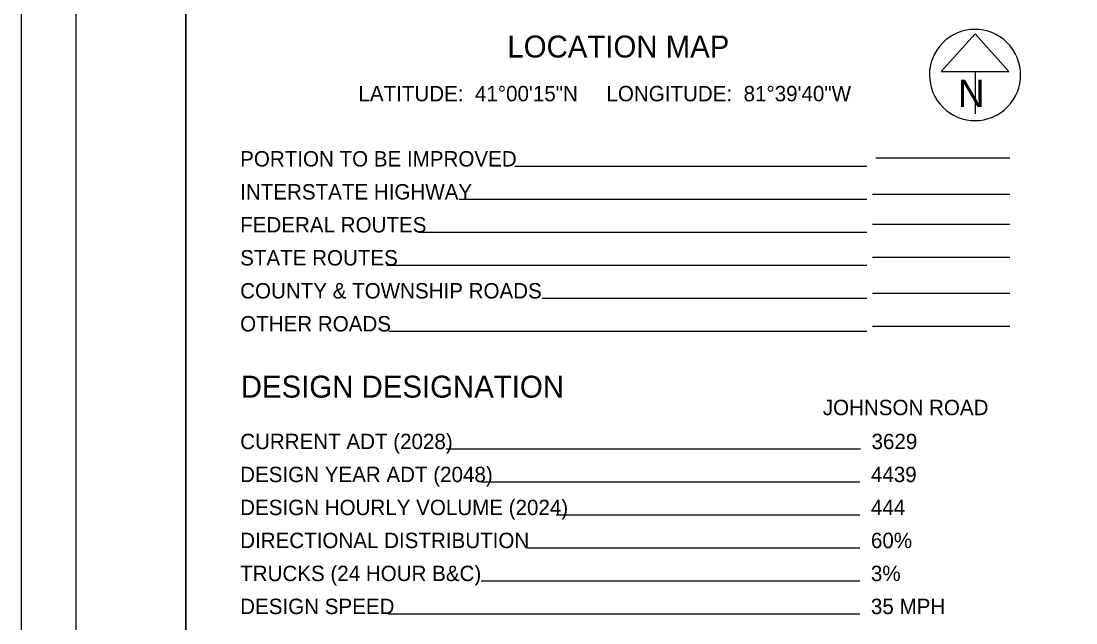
# Model space of a CAD drawing. Extents: x 0 to 34, y -5 to 22.
# Drawn here: x 0 to 9.6, y 8.45 to 13.93 of the extents above; entities that cross this region are included whole.
import ezdxf

# ---------------------------------------------------------------- set-up
doc = ezdxf.new("R2010")
doc.units = 0
for name, color, linetype in [('SH_Border', 7, 'Continuous'), ('SH_Cut_Line', 7, 'Continuous'), ('SH_Data', 7, 'Continuous'), ('SH_Text', 7, 'Continuous')]:
    doc.layers.add(name, color=color, linetype=linetype)

msp = doc.modelspace()

# ---------------------------------------------------------------- linework, layer by layer
at = {"layer": 'SH_Border'}
for points in [[(0.5, 21.5), (1.5, 21.5), (1.5, 0.5), (0.5, 0.5)], [(1.5, 21.5), (33.5, 21.5), (33.5, 0.5), (1.5, 0.5)]]:
    msp.add_lwpolyline(points, close=True, dxfattribs=at)
at = {"layer": 'SH_Cut_Line'}
msp.add_lwpolyline([(0, 0), (34, 0), (34, 22), (0, 22)], close=True, dxfattribs=at)
at = {"layer": 'SH_Data'}
for p, q in [((8.6845, 13.8091), (8.3769, 13.4678)), ((8.9921, 13.4678), (8.6845, 13.8091)), ((8.3769, 13.4678), (8.9921, 13.4678)), ((8.6845, 13.4678), (8.6845, 13.0811)), ((8.6845, 13.4353), (8.6845, 13.4353)), ((8.6845, 13.4353), (8.6845, 13.4353)), ((7.7827, 12.6813), (9, 12.6813)), ((7.7, 12.6027), (4.4937, 12.6027)), ((7.7, 12.3027), (3.9895, 12.3027)), ((9, 12.3468), (7.75, 12.3468)), ((9, 12.0751), (7.75, 12.0751)), ((7.7, 12.0027), (3.6192, 12.0027)), ((9, 11.7751), (7.75, 11.7751)), ((7.7, 11.7027), (3.3288, 11.7027)), ((9, 11.4483), (7.75, 11.4483)), ((7.7, 11.4027), (4.7452, 11.4027)), ((9, 11.1483), (7.75, 11.1483)), ((7.7, 11.1027), (3.3471, 11.1027)), ((7.6424, 10.0323), (3.871, 10.0323)), ((7.6368, 9.7323), (4.1885, 9.7323)), ((7.6368, 9.4323), (4.8723, 9.4323)), ((7.6368, 9.1323), (4.6037, 9.1323)), ((7.6368, 8.8323), (4.1885, 8.8323)), ((7.6368, 8.5323), (3.346, 8.5323))]:
    msp.add_line(p, q, dxfattribs=at)
msp.add_arc((8.6845, 13.4353), 0.4148, 129.77984, 129.76332, dxfattribs=at)

# ---------------------------------------------------------------- texts
for s, height, p in [('N', 0.25, (8.5292, 13.144)), ('DESIGN DESIGNATION', 0.2, (2, 10.5007))]:
    msp.add_text(s, height=height, dxfattribs=at).set_placement(p)
at = {"layer": 'SH_Text'}
for s, height, p in [('LOCATION MAP', 0.2, (4.4269, 13.5938)), ('LATITUDE:  41°00\'15"N     LONGITUDE:  81°39\'40"W', 0.14, (3.071, 13.1959)), ('PORTION TO BE IMPROVED', 0.14, (1.9944, 12.6027)), ('INTERSTATE HIGHWAY', 0.14, (1.9944, 12.3027)), ('FEDERAL ROUTES', 0.14, (1.9944, 12.0027)), ('STATE ROUTES', 0.14, (1.9944, 11.7027)), ('COUNTY & TOWNSHIP ROADS', 0.14, (1.9944, 11.4027)), ('OTHER ROADS', 0.14, (1.9944, 11.1027)), ('JOHNSON ROAD', 0.14, (7.2985, 10.3413)), ('CURRENT ADT (2028)', 0.14, (1.9944, 10.0323)), ('3629', 0.14, (7.7424, 10.0323)), ('DESIGN YEAR ADT (2048)', 0.14, (1.9944, 9.7323)), ('4439', 0.14, (7.7368, 9.7323)), ('DESIGN HOURLY VOLUME (2024)', 0.14, (1.9944, 9.4323)), ('444', 0.14, (7.7368, 9.4323)), ('DIRECTIONAL DISTRIBUTION', 0.14, (1.9944, 9.1323)), ('60%', 0.14, (7.7368, 9.1323)), ('TRUCKS (24 HOUR B&C)', 0.14, (1.9944, 8.8323)), ('3%', 0.14, (7.7368, 8.8323)), ('DESIGN SPEED', 0.14, (1.9944, 8.5323)), ('35 MPH', 0.14, (7.7368, 8.5323))]:
    msp.add_text(s, height=height, dxfattribs=at).set_placement(p)

doc.saveas('drawing.dxf')
